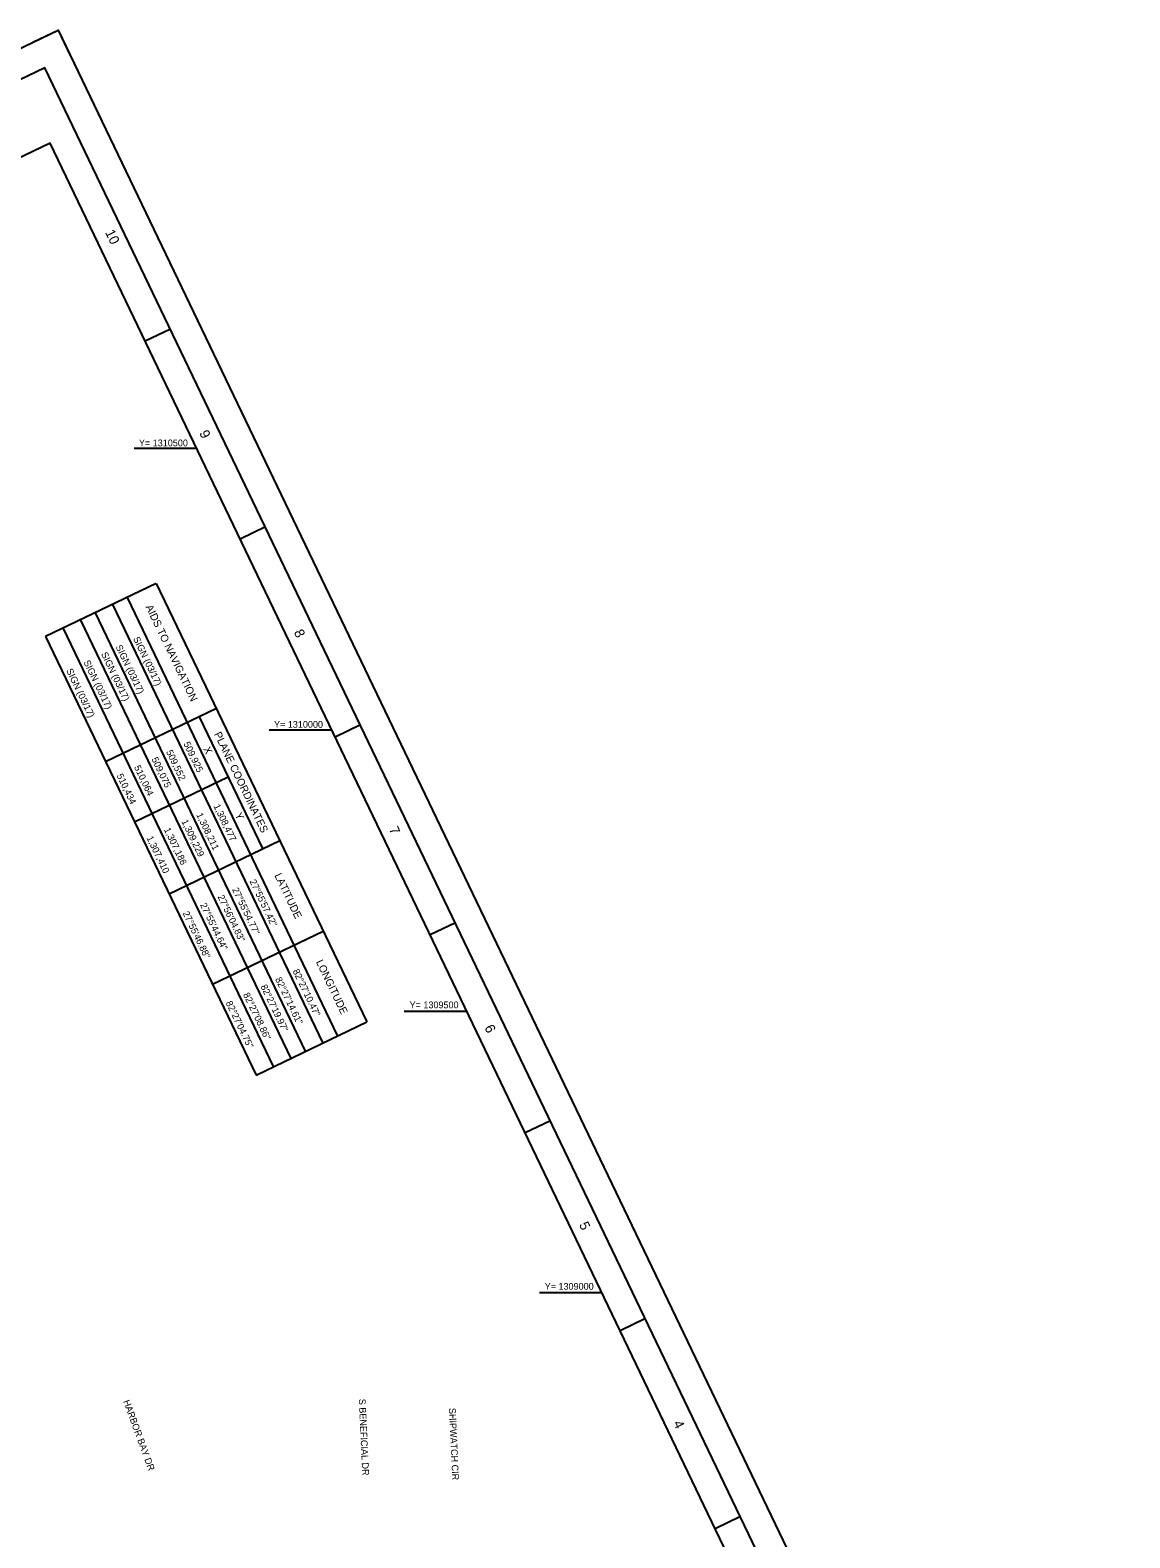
# Model space of a CAD drawing. Extents: x 507278 to 512248, y 1305805 to 1311243.
# Drawn here: x 510293 to 512248, y 1308565 to 1311243 of the extents above; entities that cross this region are included whole.
import ezdxf

# ---------------------------------------------------------------- set-up
doc = ezdxf.new("R2010")
doc.units = 0
for name, color, linetype in [('G-ANNO-NPLT', 7, 'Continuous'), ('G-ANNO-TTLB', 7, 'Continuous'), ('V-ANNO-SCHD', 7, 'Continuous'), ('V-ANNO-SYMB', 7, 'Continuous'), ('V-ROAD-IDEN', 7, 'Continuous'), ('V-TOPO-COOR-STAT', 7, 'Continuous')]:
    doc.layers.add(name, color=color, linetype=linetype)

msp = doc.modelspace()

# ---------------------------------------------------------------- linework, layer by layer
at = {"layer": 'G-ANNO-NPLT'}
msp.add_lwpolyline([(510343.2, 1311243.3), (512247.6, 1307276.8), (509182.6, 1305805.3), (507278.2, 1309771.7)], close=True, dxfattribs=at)
msp.add_lwpolyline([(510298.1, 1311221.7), (510343.2, 1311243.3), (510364.8, 1311198.3)], dxfattribs=at)
at = {"layer": 'G-ANNO-TTLB'}
for p, q in [((510542.7, 1310712.4), (510497.6, 1310690.7)), ((510711.5, 1310360.8), (510666.4, 1310339.1)), ((510711.5, 1310360.8), (510666.4, 1310339.1)), ((510880.3, 1310009.2), (510835.2, 1309987.6)), ((511049.1, 1309657.6), (511004, 1309636)), ((511217.9, 1309306), (511172.8, 1309284.4)), ((511386.7, 1308954.5), (511341.6, 1308932.8)), ((511555.5, 1308602.9), (511510.4, 1308581.3))]:
    msp.add_line(p, q, dxfattribs=at)
for points in [[(507344.9, 1309748.3), (509206, 1305872), (512180.9, 1307300.3), (510319.8, 1311176.6)], [(512114.2, 1307323.7), (510328.8, 1311042.3), (507444.1, 1309657.3), (509229.5, 1305938.7)]]:
    msp.add_lwpolyline(points, close=True, dxfattribs=at)
at = {"layer": 'V-ANNO-SCHD'}
for p, q in [((510517.6, 1310260.4), (510320.9, 1310165.9)), ((510517.6, 1310260.4), (510891.6, 1309481.4)), ((510465.6, 1310235.4), (510839.6, 1309456.5)), ((510408.7, 1310208), (510782.4, 1309429.6)), ((510439.6, 1310222.9), (510813.5, 1309444)), ((510351.8, 1310180.7), (510725.5, 1309402.2)), ((510382.7, 1310195.5), (510756.6, 1309416.6)), ((510320.9, 1310165.9), (510694.8, 1309387)), ((510624.4, 1310038), (510427.6, 1309943.5)), ((510594, 1310023.4), (510706.9, 1309788.4)), ((510645.5, 1309916.3), (510479.1, 1309836.4)), ((510737.2, 1309803), (510540.5, 1309708.5)), ((510814.4, 1309642.2), (510617.7, 1309547.7)), ((510694.8, 1309387), (510891.6, 1309481.4))]:
    msp.add_line(p, q, dxfattribs=at)
at = {"layer": 'V-TOPO-COOR-STAT'}
for p, q in [((510589.2, 1310500), (510478.2, 1310500)), ((510829.2, 1310000), (510718.3, 1310000)), ((511069.3, 1309500), (510958.3, 1309500)), ((511309.3, 1309000), (511198.4, 1309000))]:
    msp.add_line(p, q, dxfattribs=at)

# ---------------------------------------------------------------- texts
at = {"layer": 'G-ANNO-TTLB'}
for s, p in [('10', (510426.2, 1310884.3)), ('9', (510593.5, 1310527.8)), ('8', (510761.6, 1310173.9)), ('7', (510930.4, 1309823.8)), ('6', (511100.3, 1309471.7)), ('5', (511268.4, 1309121.5)), ('4', (511435.7, 1308768.7))]:
    msp.add_text(s, height=17.5, rotation=295.6468, dxfattribs=at).set_placement(p)
at = {"layer": 'V-ANNO-SCHD'}
for s, height, p in [('AIDS TO NAVIGATION', 13.471, (510498.1, 1310218.9)), ('PLANE COORDINATES', 13.471, (510619.9, 1309992.9)), ('X', 13.5, (510600.6, 1309966.5)), ('Y', 13.5, (510656.7, 1309849.6)), ('LATITUDE', 13.47, (510727.1, 1309741.9)), ('LONGITUDE', 13.47, (510800.9, 1309588.2))]:
    msp.add_text(s, height=height, rotation=295.6468, dxfattribs=at).set_placement(p)
at = {"layer": 'V-ANNO-SYMB'}
for s, p in [('SIGN (03/17)', (510444.9, 1310148.1)), ('SIGN (03/17)', (510476, 1310162.5)), ('SIGN (03/17)', (510388, 1310120.8)), ('SIGN (03/17)', (510419.1, 1310135.2)), ('SIGN (03/17)', (510357.1, 1310105.9)), ('509,552', (510534.6, 1309961.3)), ('509,925', (510565.6, 1309975.8)), ('510,064', (510477.7, 1309934)), ('509,075', (510508.7, 1309948.5)), ('510,434', (510446.8, 1309919.2)), ('1,308,477', (510618.8, 1309865.1)), ('1,309,229', (510561.9, 1309837.8)), ('1,308,211', (510588.2, 1309849.6)), ('1,307,410', (510499.9, 1309808.5)), ('1,307,186', (510530.8, 1309823.3)), ('27%%D55\'57.42"', (510683, 1309731.3)), ('27%%D56\'04.83"', (510626.1, 1309704)), ('27%%D55\'54.77"', (510651.9, 1309716.9)), ('27%%D55\'46.88"', (510564.1, 1309674.7)), ('27%%D55\'44.64"', (510595, 1309689.6)), ('82%%D27\'14.61"', (510728.5, 1309557.5)), ('82%%D27\'10.47"', (510759.6, 1309571.9)), ('82%%D27\'08.86"', (510671.5, 1309530.2)), ('82%%D27\'19.97"', (510702.6, 1309544.6)), ('82%%D27\'04.75"', (510640.7, 1309515.4))]:
    msp.add_text(s, height=12, rotation=295.6468, dxfattribs=at).set_placement(p)
at = {"layer": 'V-ROAD-IDEN'}
for s, rotation, p in [('HARBOR BAY DR', 290.0832, (510458.5, 1308807.6)), ('S BENEFICIAL DR', 272.6107, (510877.5, 1308811.7)), ('SHIPWATCH CIR', 272.6107, (511037.6, 1308795.5))]:
    msp.add_text(s, height=12, rotation=rotation, dxfattribs=at).set_placement(p)
at = {"layer": 'V-TOPO-COOR-STAT'}
for s, p in [('Y= 1310500', (510486.7, 1310504.1)), ('Y= 1310000', (510726.8, 1310004.1)), ('Y= 1309500', (510967.7, 1309505.8)), ('Y= 1309000', (511207.8, 1309005.8))]:
    msp.add_text(s, height=12, rotation=360, dxfattribs=at).set_placement(p)

doc.saveas('drawing.dxf')
